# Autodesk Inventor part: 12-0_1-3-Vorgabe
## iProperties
Created: 2006-01
Part Number: 12-0_1-3-Vorgabe
Document SubType Name: Modeling
Designer: Armin Gräf
Stock Number: 12-0_1-3-Vorgabe
Author: Armin Gräf
